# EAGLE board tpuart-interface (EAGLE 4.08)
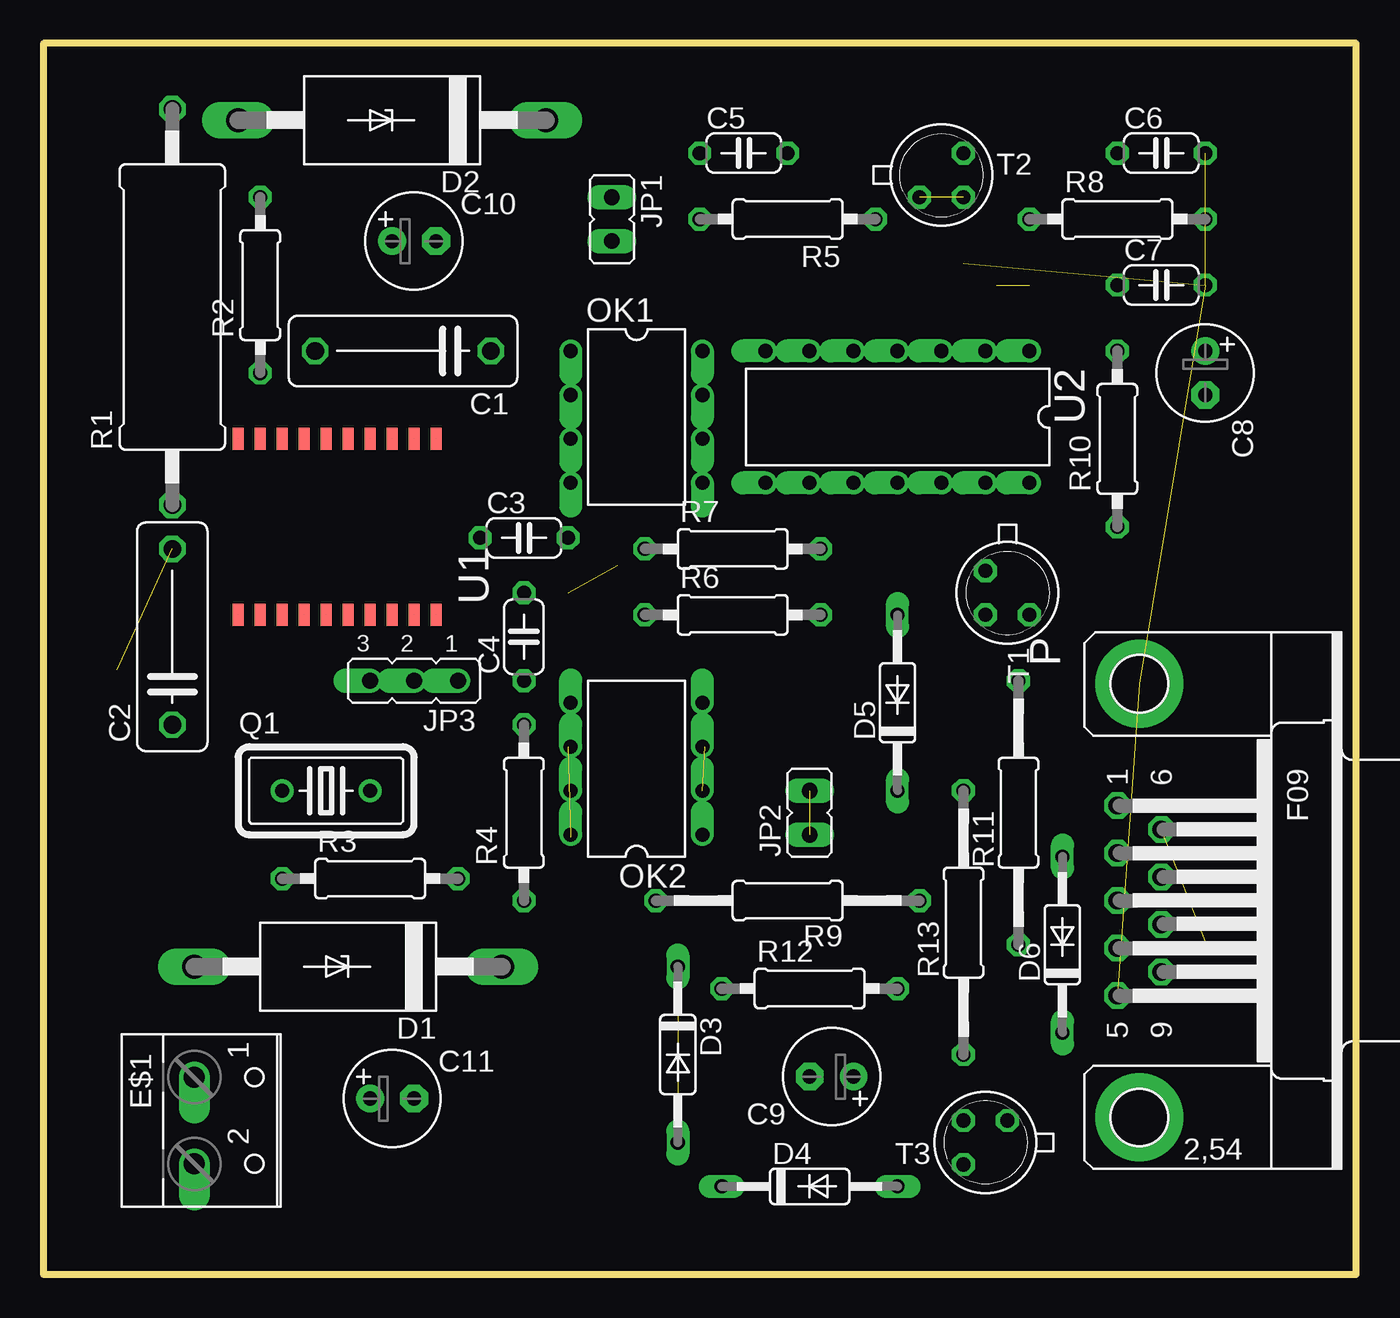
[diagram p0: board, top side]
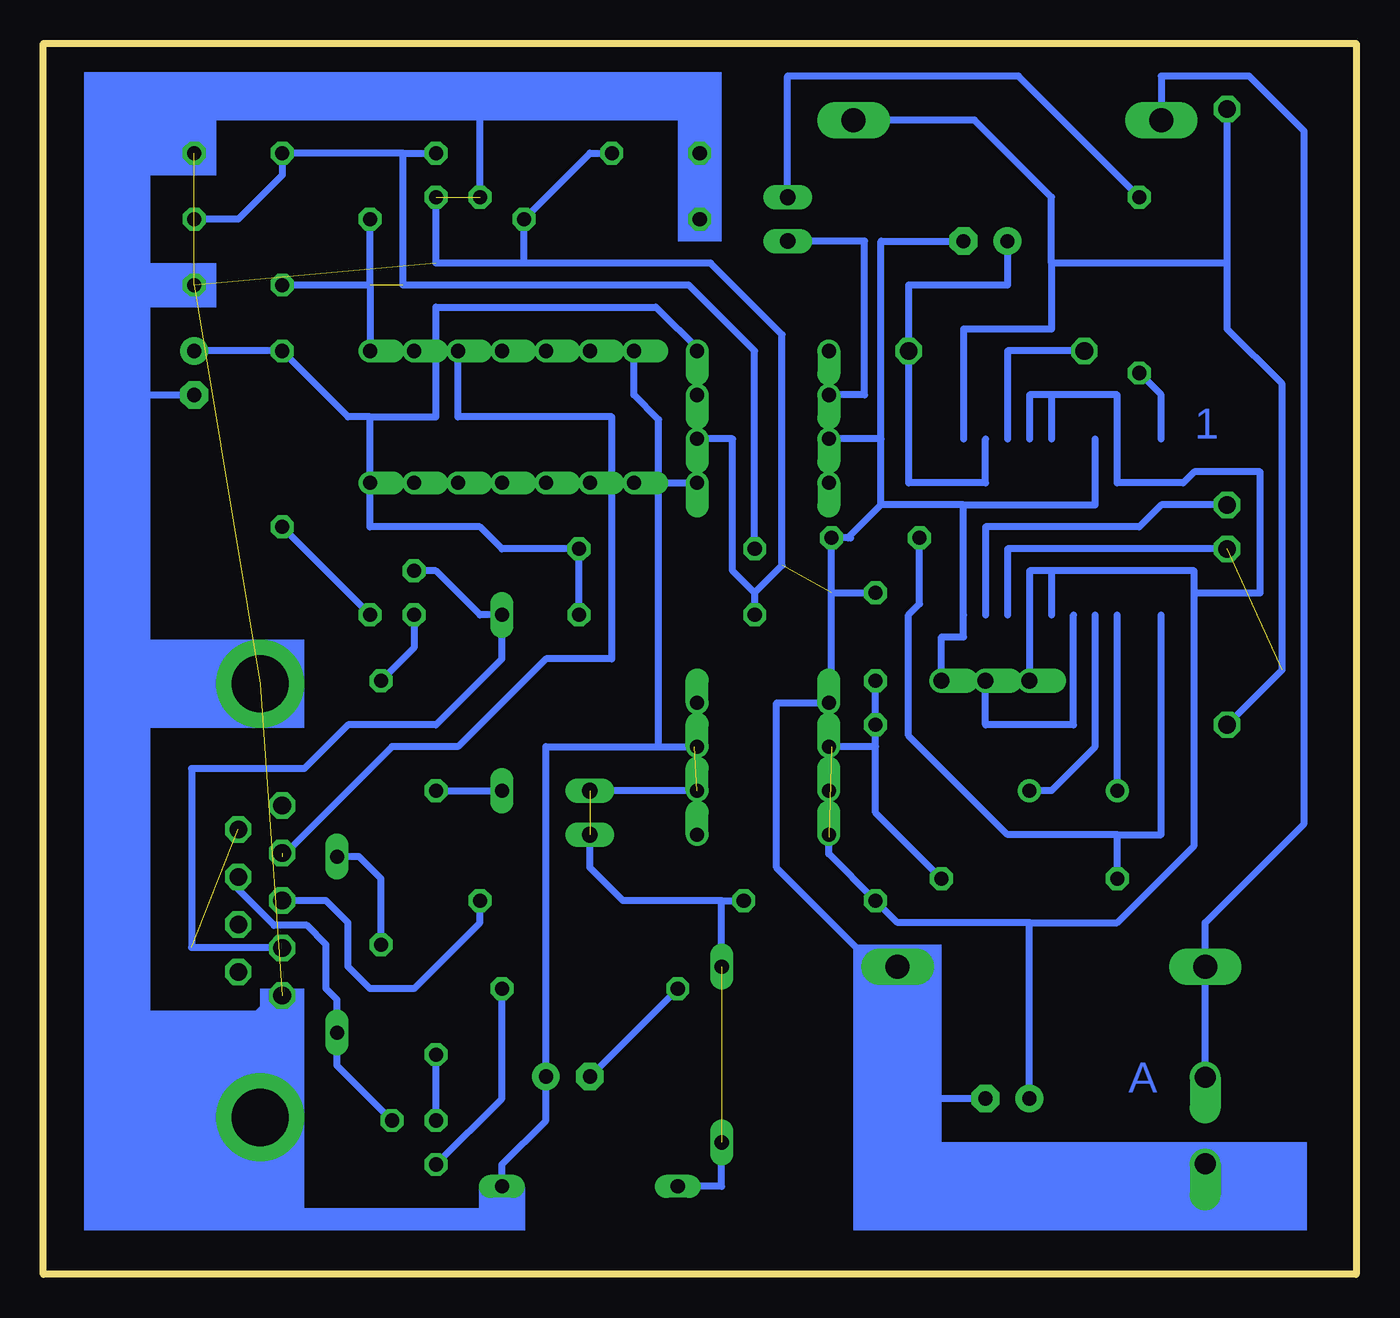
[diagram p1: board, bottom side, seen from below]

Size 75.87 x 71.11 mm. Coordinates in mm from the lower left corner, seen from the top.
Outline: 0,0 75.87,0 75.87,71.11 0,71.11 0,0
Copper layers used: Bottom

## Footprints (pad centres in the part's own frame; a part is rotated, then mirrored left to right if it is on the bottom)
C102-043X133 = drill 1.016 octagon: 1 -5.08,0; 2 5.08,0
C050-024X044 = drill 0.813 octagon: 1 -2.54,0; 2 2.54,0
E2,5-6 = drill 0.813 pad 1.6 round: + -1.27,0 | drill 0.813 pad 1.6 octagon: - 1.27,0
CB429-17 = drill 1.397 long: A 8.89,0; C -8.89,0
DO35-10 = drill 0.813 long: A 5.08,0; C -5.08,0
W237-102 = drill 1.194 offset: 1 -2.5,-1.27; 2 2.5,-1.27
TP-UART-BOARD-REAL = smd 0.635 x 1.27: P$1 0,0; P$2 1.27,0; P$3 2.54,0; P$4 3.81,0; P$5 5.08,0; P$6 6.35,0; P$7 7.62,0; P$8 8.89,0; P$9 10.16,0; P$10 11.43,0; P$11 0,10.16; P$12 1.27,10.16; P$13 2.54,10.16; P$14 3.81,10.16; P$15 5.08,10.16; P$16 6.35,10.16; P$17 7.62,10.16; P$18 8.89,10.16; P$19 10.16,10.16; P$20 11.43,10.16
JP1 = drill 0.914 long: 1 0,-1.27; 2 0,1.27
JP2 = drill 0.914 offset: 1 -2.54,0; 2 0,0; 3 2.54,0
DIL08 = drill 0.813 offset: 1 -3.81,-3.81; 2 -1.27,-3.81; 3 1.27,-3.81; 4 3.81,-3.81; 5 3.81,3.81; 6 1.27,3.81; 7 -1.27,3.81; 8 -3.81,3.81
F09HP = drill 1.016 octagon: 1 -5.486,-1.27; 2 -2.743,-1.27; 3 0,-1.27; 4 2.743,-1.27; 5 5.486,-1.27; 6 -4.115,1.27; 7 -1.372,1.27; 8 1.372,1.27; 9 4.115,1.27 | drill 3.302 pad 5.08 round: G1 -12.522,0; G2 12.522,0
HC18U-V = drill 0.813 round: 1 -2.54,0; 2 2.54,0
0617/22 = drill 1.016 octagon: 1 -11.43,0; 2 11.43,0
0207/10 = drill 0.813 octagon: 1 -5.08,0; 2 5.08,0
0207/15 = drill 0.813 octagon: 1 -7.62,0; 2 7.62,0
TO18 = drill 0.813 octagon: 1 -1.27,-1.27; 2 1.27,-1.27; 3 1.27,1.27
DIL14 = drill 0.813 offset: 1 -7.62,-3.81; 2 -5.08,-3.81; 3 -2.54,-3.81; 4 0,-3.81; 5 2.54,-3.81; 6 5.08,-3.81; 7 7.62,-3.81; 8 7.62,3.81; 9 5.08,3.81; 10 2.54,3.81; 11 0,3.81; 12 -2.54,3.81; 13 -5.08,3.81; 14 -7.62,3.81

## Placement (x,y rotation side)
C1  47n  [C102-043X133]  20.79,53.34 180 top
C2  47n  [C102-043X133]  7.46,36.82 90 top
C3  47p  [C050-024X044]  27.77,42.54 0 top
C4  47p  [C050-024X044]  27.77,36.82 90 top
C5  47p  [C050-024X044]  40.48,64.77 0 top
C6  47p  [C050-024X044]  64.61,64.77 0 top
C7  47p  [C050-024X044]  64.61,57.14 0 top
C8  10µ  [E2,5-6]  67.14,52.06 270 top
C9  10µ  [E2,5-6]  45.55,11.43 180 top
C10  100µ  [E2,5-6]  21.42,59.68 0 top
C11  6µ8  [E2,5-6]  20.16,10.16 0 top
D1  P6KE51CA  [CB429-17]  17.62,17.77 180 top
D2  1N5408  [CB429-17]  20.16,66.67 180 top
D3  1N4148  [DO35-10]  36.66,12.7 270 top
D4  1N4148  [DO35-10]  44.28,5.08 0 top
D5  1N4148  [DO35-10]  49.36,33.02 90 top
D6  1N4148  [DO35-10]  58.89,19.04 90 top
E$1  [W237-102]  9.99,8.89 270 top
E$2  [TP-UART-BOARD-REAL]  11.27,38.09 0 top
JP1  [JP1]  32.85,60.96 180 top
JP2  [JP1]  44.28,26.66 0 top
JP3  [JP2]  21.42,34.28 180 top
OK1  HP4503  [DIL08]  34.28,49.52 270 top
OK2  HP4503  [DIL08]  34.28,29.2 90 top
P  [F09HP]  63.33,21.59 270 top
Q1  4,915MHZ  [HC18U-V]  16.34,27.94 0 top
R1  68/1W  [0617/22]  7.46,55.88 90 top
R2  1k  [0207/10]  12.54,57.14 90 top
R3  4k7  [0207/10]  18.88,22.86 0 top
R4  22k  [0207/10]  27.77,26.66 90 top
R5  47k  [0207/10]  43.02,60.96 180 top
R6  22k  [0207/10]  39.84,38.09 0 top
R7  22k  [0207/10]  39.84,41.91 0 top
R8  4k7  [0207/10]  62.06,60.96 0 top
R9  3k  [0207/15]  43.02,21.59 180 top
R10  150  [0207/10]  62.06,48.26 90 top
R11  68k  [0207/15]  56.35,26.66 90 top
R12  150  [0207/10]  44.28,16.5 0 top
R13  68k  [0207/15]  53.17,20.31 90 top
T1  BC177  [TO18]  55.72,39.37 270 top
T2  BC107  [TO18]  51.91,63.49 0 top
T3  BC107  [TO18]  54.44,7.61 180 top
U2  4011N  [DIL14]  49.36,49.52 180 top

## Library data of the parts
C1-C11 R1-R13 = rcl
D1-D6 = diode
E$1 = con-wago-500
E$2 = TPUART
JP1-JP3 = jumper
OK1 OK2 U2 = 40xx
P = con-subd
Q1 = crystal
T1 = transistor-pnp
T2 T3 = transistor-npn

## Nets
CTS: D6.C T3.1
DSR: D5.A P.6 T1.1
N$8: Q1.1
N$9: D2.C E$2.P$20
N$11: R12.2 T3.3
N$12: T3.2
N$16: R11.2 T1.2
N$19: R10.1 T1.3
N$20: C3.1 E$2.P$1 R3.1
N$21: C4.2 C5.2 P.5 P.G1 R5.1 R6.1 T2.1 T2.2
N$28: C4.1 C11.+ E$2.P$17 JP3.3 R3.2 R4.1 R4.2
RXD: P.2 U2.3
S$2: P.8
S$3: JP1.2 OK1.2
S$4: E$2.P$4 Q1.2
S$5: C8.-
S$6: JP1.1 R2.2
S$7: E$2.P$5 JP3.2
S$8: D1.A D2.A
S$9: C9.- R12.1
S$12: E$2.P$11 R2.1
S$13: D6.A R11.1
S$14: C7.1 R7.1 R8.1 R8.2 T2.3 U2.1 U2.2
S$15: D3.A D3.C D4.A D4.C JP2.1 JP2.2 R9.2 U2.7
S$16: E$2.P$18
S$17: R5.2
S$19: C11.-
S$20: E$2.P$9
S$21: R6.2 R7.2 R10.2 U2.14
S$22: C10.+ E$2.P$19
S$23: D5.C R13.2
S$24: C10.- E$2.P$10 JP3.1
TXD: P.3 R9.1

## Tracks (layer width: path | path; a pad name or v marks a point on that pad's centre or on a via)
CTS
  Bottom 0.406: T3.1 58.89,12.06 D6.C 58.89,15.87 59.53,16.5 59.53,19.04 60.64,20.16 62.54,20.16 64.76,22.38
DSR  (1 unrouted)
  Bottom 0.406: T1.1 53.17,40.63 50.64,38.09 D5.A 49.36,35.55 53.17,31.74 58.25,31.74 60.8,29.2 67.3,29.2 67.3,18.89 62.06,18.89
N$8
  Bottom 0.406: Q1.1 13.81,38.09
N$9  (2 unrouted)
  Bottom 0.406: E$2.P$20 22.7,54.6 17.62,54.6 17.62,58.41 | 17.62,58.41 17.62,62.23 22.06,66.67 D2.C | 20.16,38.09 20.16,41.91 7.46,41.91 | 7.46,31.74 4.28,34.92 4.28,51.43 7.46,54.6 7.46,58.41 | 7.46,58.41 7.46,66.67 | 7.46,58.41 17.62,58.41
N$11
  Bottom 0.406: R12.2 49.36,10.16 T3.3
N$12
  Bottom 0.406: T3.2 53.17,12.7
N$16
  Bottom 0.406: T1.2 54.44,36.19 R11.2
N$19
  Bottom 0.406: T1.3 R10.1
N$20  (1 unrouted)
  Bottom 0.406: E$2.P$1 11.27,25.39 13.81,25.39 | 13.81,25.39 20.16,25.39 25.87,31.11 25.87,38.09 25.23,38.73 C3.1 | R3.1 13.81,25.39
N$21  (6 unrouted)
  Bottom 0.406: T2.1 50.64,67.31 | 67.14,64.77 70.95,64.77 | C5.2 44.28,64.77 R5.1 48.09,58.41 | 67.14,57.14 69.69,57.14 | T2.2 53.17,58.41 48.09,58.41 | 37.94,48.26 36.03,48.26 36.03,40.63 34.76,39.37 | 48.09,58.41 37.3,58.41 33.17,54.29 33.17,40.95 34.76,39.37 | 34.76,39.37 R6.1 | 30.31,39.37 30.31,42.54 29.2,42.54 | 30.31,39.37 C4.2 | 30.31,39.37 30.31,33.02 33.49,33.02 33.49,23.49 27.77,17.77
N$28  (2 unrouted)
  Bottom 0.406: E$2.P$17 18.88,50.8 17.62,50.8 | 17.62,50.8 17.62,48.26 | 17.62,50.8 13.81,50.8 13.81,45.71 9.99,45.71 9.36,46.35 5.55,46.35 5.55,39.37 9.36,39.37 | JP3.3 18.88,40.63 17.62,40.63 | 17.62,40.63 17.62,38.09 | 17.62,40.63 9.36,40.63 9.36,39.37 | 9.36,39.37 9.36,24.76 13.81,20.31 18.88,20.31 | C11.+ 18.88,20.31 | C4.1 R4.2 27.77,30.48 | 27.77,30.48 30.31,30.48 | 30.47,25.24 30.47,24.28 R4.1 26.5,20.31 18.88,20.31 | 27.77,30.48 27.77,26.66 R3.2
RXD  (1 unrouted)
  Bottom 0.406: 62.06,24.12 55.72,30.48 51.91,30.48 46.82,35.55 43.02,35.55 43.02,49.52 51.91,49.52 U2.3
S$1
  Bottom 0.406: 62.06,16.5 64.61,13.96 69.69,13.96
S$3
  Bottom 0.406: JP1.2 28.41,59.68 28.41,50.8 OK1.2
S$4  (1 unrouted)
  Bottom 0.406: E$2.P$4 15.08,30.48 17.62,27.94 Q1.2
S$5
  Bottom 0.406: 70.95,50.8 C8.-
S$6
  Bottom 0.406: R2.2 19.52,69.21 32.85,69.21 JP1.1
S$7  (1 unrouted)
  Bottom 0.406: JP3.2 21.42,31.74 16.34,31.74 E$2.P$5
S$8
  Bottom 0.406: D2.A 11.27,69.21 6.19,69.21 3.01,66.04 3.01,26.03 8.72,20.31 D1.A 8.72,11.43
S$9
  Bottom 0.406: C9.- R12.1
S$10
  Bottom 0.406: 72.22,46.98 70.95,48.26
S$11
  Bottom 0.406: 64.61,22.38 64.61,22.86
S$12  (1 unrouted)
  Bottom 0.406: E$2.P$11 11.27,50.8 R2.1
S$13
  Bottom 0.406: R11.1 56.35,22.86 57.62,24.12 D6.A
S$14  (1 unrouted)
  Bottom 0.406: U2.2 U2.1 56.98,57.14 | 56.98,57.14 R8.1 | 56.98,57.14 C7.1 | 55.08,64.77 62.06,64.77 62.06,63.49 64.61,60.96 R8.2 | 55.08,64.77 T2.3 | 55.08,64.77 55.08,57.14 38.57,57.14 34.76,53.34 R7.1
S$15  (3 unrouted)
  Bottom 0.406: 36.66,21.59 R9.2 | D3.C 36.66,21.59 | D3.A 36.66,5.08 D4.C | 36.66,21.59 42.38,21.59 44.28,23.49 JP2.1 | U2.7 41.74,50.8 40.32,49.37 40.32,30.48 | 38.09,27.94 JP2.2 | 40.32,30.48 38.25,30.48 | 40.32,30.48 46.82,30.48 46.82,8.89 49.36,6.34 D4.A
S$16  (1 unrouted)
  Bottom 0.406: E$2.P$18 20.16,53.34 15.71,53.34
S$18
  Bottom 0.406: 40.32,45.71 38.25,45.71
S$19
  Bottom 0.406: C11.- 26.5,10.16
S$20  (1 unrouted)
  Bottom 0.406: 7.46,44.45 11.27,44.45 12.54,43.17 21.42,43.17 E$2.P$9
S$21
  Bottom 0.406: R6.2 R7.2 49.36,41.91 50.64,43.17 56.98,43.17 U2.14 56.98,49.52 | 67.14,53.34 R10.2 58.25,49.52 56.98,49.52 | 56.98,49.52 53.17,49.52 53.17,55.88 40.48,55.88 37.94,53.34
S$22  (1 unrouted)
  Bottom 0.406: C10.+ 20.16,57.14 25.87,57.14 25.87,45.71 21.42,45.71 E$2.P$19
S$23
  Bottom 0.406: R13.2 D5.C
S$24  (1 unrouted)
  Bottom 0.406: C10.- 27.46,59.68 27.46,48.26 | 27.46,48.26 30.31,48.26 | 27.46,44.45 27.46,48.26 | 15.08,48.26 15.08,44.45 22.7,44.45 | 22.7,44.45 27.46,44.45 | 22.7,44.45 E$2.P$10 22.7,36.82 23.96,36.82 JP3.1 | 27.46,44.45 29.36,42.54
TXD
  Bottom 0.406: R9.1 50.64,20.31 54.44,16.5 56.98,16.5 58.25,17.77 58.25,20.31 59.53,21.59 P.3
(copper drawn outside any net)
  shapes: Bottom area x23

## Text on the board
Bottom: 1 | A
tNames: U1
